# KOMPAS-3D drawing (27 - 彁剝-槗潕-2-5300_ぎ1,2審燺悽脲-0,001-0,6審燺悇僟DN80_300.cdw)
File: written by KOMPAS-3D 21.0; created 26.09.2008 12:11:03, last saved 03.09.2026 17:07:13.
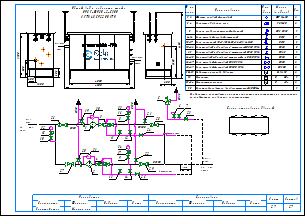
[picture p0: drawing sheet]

Sheets 1-2: A3, landscape

Document properties: Наименование: Макро:21; Автор: RaskoAdmin; Форматы листов документа: 2xA3; Полное имя файла: \\UR38nt01\Departments\КТО\КБ ПУРДГ\Заявки\Прайс-лист на типовые шкафы ГРПШ\ПРДГ_стандарт_20_03_2026\ПРДГ с РДГ(Н, В)\ПРДГ-ШУЭО-2-5300_до1,2МПа_Рвых-0,001-0,6МПа_РДГ_DN80_300.cdw

Title block, sheet 1: Наименование: Пункт учета газа / ПУГ-Ш-400-Р / ЛГТИ.485922.001ТУ; designation: ЛГТИ.03.4411141; sheet number: 1; Количество листов документа: 2; organisation: ООО "ЭЛЬСТЕР Газэлектроника"; Форматы листов документа: A3; stored path: C:\Рабочие документы\Компас\ПУГ\Схема.cdw; Разработал: Устинов; Проверил: Кошкин; Утвердил: Кошкин
Title block, sheet 2: sheet number: 2; stored path: D:\Рабочие документы\Заявки\ПУРДГ\ПУРДГ-ШУЭО-2-100-Р 4411220.cdw; designation, second copy: ЛГТИ.03.4411141-

Views: Вид 1, Вид 2
Referenced files: wcvoit.frw
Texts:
  Normal
  № на
  схеме
  Усл.
  обозн.
  Марка
  (модель)
  Кол.
  Фильтр газовый фланцевый
  ФГ 16-80
  Регулятор давления газа
  РДГ-50
  Клапан предохранительный сбросной
  ПСК DN25
  Кран шаровой газовый латунный
  DN15
  Кран кнопочный VE-РАСКО-НЗ-1,6-G1/2-М20
  Кран шаровой "под приварку" штуцерный DN20 PN16
  Кран шаровой "под приварку" штуцерный DN25 PN16
  Кран шаровой "под приварку" штуцерный п/п DN20 PN16
  DN20
  DN25
  Кран шаровой фланцевый DN80 PN16
  Кран шаровой фланцевый DN300 PN16
  DN80
  DN300
  Индикатор перепада давления
  Delta 15
  Манометр
  Манометр-напоромер
  Электрообогреватель взрывозащищенный 2000Вт
  0...     МПа
  0...     кПа
  Общий вид и габариты шкафа
  ПРДГ-ШУЭО-2-5300
  Выход газа
  Вход газа
  logo-rasko-ge.png
  Вход
  газа
  PDI
  Выход
  Р=     кПа
  DN50
  Импульс DN20
  ≥5DN
  HYSWLongFangSong
  Р=       МПа
  Схема открывания дверей
  Предприятие изготовитель может заменять комплектующие на аналогичные,
  не ухудшающие заявленных характеристик.
  Должность
  Конструктор
  Фамилия
  Подпись
  Дата
  Согласовано
  Максимкин
  Лист
  Листов
  POLYLINE_STYLE_0.18_RGB_0_0_0
  POLYLINE_STYLE_0.50_RGB_0_0_0
  POLYLINE_STYLE_0.34_RGB_0_0_0
  PHANTOM_RGB_0_0_0_SC_1_THICK_0.18
  K5LT_THIN_RGB_0_0_0_THICK_0.18
  K5LT32769_RGB_0_0_0_THICK_0.18
  K5LT12_RGB_0_0_0_SC_1_THICK_0.18
  K5LT_DASHED_RGB_0_0_0_SC_1_THICK_0.18
  ACISOTGL_RGB_0_0_0_SC_0.8_THICK_0.25
  CONTINUOUS_RGB_0_127_31_THICK_0.3
  CONTINUOUS_RGB_0_0_255_THICK_0.35
  CONTINUOUS_RGB_255_0_0_THICK_0.35
  POLYLINE_STYLE_0.25_RGB_0_0_0
  CONTINUOUS_RGB_0_0_0_THICK_0.5
  POLYLINE_STYLE_0.35_RGB_0_0_255
  CONTINUOUS_RGB_0_0_0_THICK_0.4
  CONTINUOUS_RGB_0_0_0_THICK_0.35
  Без оформления
Dimensions and other numbers on the sheet: 1; 1, 2; 2; 3, 4; 5; 6-14; 9; 15-17; 3; 18-22; 23; 24-25; 26-27; 28-29; 30-31; 32; 33-34; 35; 600; 1200; 500; 305; 2200; 4300; 1300; 4130; 4000; 4; 10; 27; 28; 29; 8; 12; 19; 20; 21; 22; 25; 24; 30; 31; 15; 16; 26; 6; 7; 11; 14; 13; 33; 17; 34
